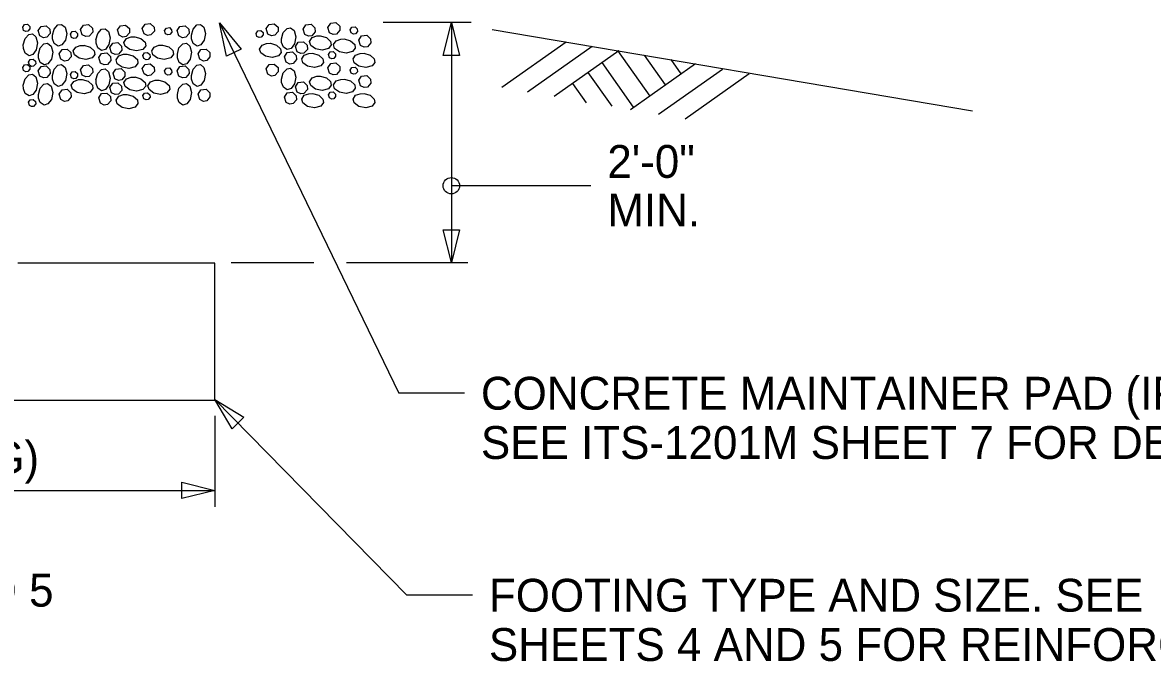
# Model space of a CAD drawing. Extents: x 3829340 to 3831660, y 499389 to 501171.
# Drawn here: x 3829574 to 3829677.1, y 499641 to 499699.3 of the extents above; entities that cross this region are included whole.
import ezdxf

# ---------------------------------------------------------------- set-up
doc = ezdxf.new("R2010")
doc.units = 0
for name, color, linetype in [('Barrier', 7, 'Continuous'), ('DIM TXT', 7, 'Continuous'), ('foundation', 7, 'Continuous'), ('grade', 7, 'Continuous')]:
    doc.layers.add(name, color=color, linetype=linetype)

msp = doc.modelspace()

# ---------------------------------------------------------------- linework, layer by layer
at = {"layer": 'Barrier'}
for points in [[(3829574.07, 499698.59), (3829573.98, 499698.89), (3829574.14, 499699.12), (3829574.42, 499699.15), (3829574.63, 499698.96), (3829574.64, 499698.73), (3829574.45, 499698.52), (3829574.27, 499698.5), (3829574.07, 499698.59)], [(3829575.55, 499698.09), (3829575.39, 499698.57), (3829575.66, 499698.96), (3829576.12, 499699.02), (3829576.47, 499698.69), (3829576.49, 499698.32), (3829576.18, 499697.97), (3829575.88, 499697.92), (3829575.55, 499698.09)], [(3829576.7, 499698.14), (3829576.86, 499698.71), (3829577.2, 499699.09), (3829577.53, 499699.14), (3829577.85, 499698.89), (3829578, 499698.31), (3829577.88, 499697.69), (3829577.57, 499697.26), (3829577.22, 499697.15), (3829576.86, 499697.39), (3829576.71, 499697.81), (3829576.7, 499698.17)], [(3829578.43, 499697.95), (3829578.34, 499698.24), (3829578.5, 499698.48), (3829578.78, 499698.51), (3829578.99, 499698.32), (3829579, 499698.09), (3829578.82, 499697.88), (3829578.64, 499697.85), (3829578.43, 499697.95)], [(3829579.42, 499698.18), (3829579.27, 499698.67), (3829579.53, 499699.06), (3829580, 499699.12), (3829580.35, 499698.79), (3829580.37, 499698.42), (3829580.06, 499698.07), (3829579.76, 499698.02), (3829579.42, 499698.18)], [(3829580.67, 499697.74), (3829580.83, 499698.31), (3829581.17, 499698.69), (3829581.5, 499698.74), (3829581.83, 499698.49), (3829581.98, 499697.91), (3829581.86, 499697.3), (3829581.54, 499696.86), (3829581.19, 499696.76), (3829580.84, 499696.99), (3829580.68, 499697.41), (3829580.68, 499697.77)], [(3829582.8, 499698.14), (3829582.64, 499698.63), (3829582.9, 499699.02), (3829583.37, 499699.08), (3829583.72, 499698.75), (3829583.74, 499698.38), (3829583.43, 499698.03), (3829583.13, 499697.98), (3829582.8, 499698.14)], [(3829585.06, 499698.29), (3829584.9, 499698.77), (3829585.17, 499699.17), (3829585.63, 499699.22), (3829585.98, 499698.9), (3829586, 499698.52), (3829585.69, 499698.17), (3829585.39, 499698.12), (3829585.06, 499698.29)], [(3829587.03, 499698.28), (3829586.94, 499698.57), (3829587.1, 499698.8), (3829587.38, 499698.84), (3829587.58, 499698.64), (3829587.6, 499698.42), (3829587.41, 499698.21), (3829587.23, 499698.18), (3829587.03, 499698.28)], [(3829588.23, 499698.09), (3829588.07, 499698.57), (3829588.33, 499698.96), (3829588.8, 499699.02), (3829589.15, 499698.69), (3829589.17, 499698.32), (3829588.86, 499697.97), (3829588.56, 499697.92), (3829588.23, 499698.09)], [(3829589.38, 499698.14), (3829589.54, 499698.71), (3829589.88, 499699.09), (3829590.21, 499699.14), (3829590.53, 499698.89), (3829590.68, 499698.31), (3829590.56, 499697.69), (3829590.25, 499697.26), (3829589.9, 499697.15), (3829589.54, 499697.39), (3829589.39, 499697.81), (3829589.38, 499698.17)], [(3829595.37, 499698.03), (3829595.28, 499698.32), (3829595.44, 499698.56), (3829595.72, 499698.59), (3829595.93, 499698.39), (3829595.94, 499698.17), (3829595.76, 499697.96), (3829595.58, 499697.93), (3829595.37, 499698.03)], [(3829596.36, 499698.26), (3829596.21, 499698.75), (3829596.47, 499699.14), (3829596.94, 499699.2), (3829597.29, 499698.87), (3829597.31, 499698.49), (3829597, 499698.14), (3829596.7, 499698.1), (3829596.36, 499698.26)], [(3829597.61, 499697.82), (3829597.77, 499698.39), (3829598.11, 499698.77), (3829598.44, 499698.82), (3829598.77, 499698.57), (3829598.92, 499697.99), (3829598.8, 499697.37), (3829598.48, 499696.94), (3829598.13, 499696.83), (3829597.78, 499697.07), (3829597.62, 499697.49), (3829597.62, 499697.85)], [(3829599.74, 499698.22), (3829599.58, 499698.71), (3829599.84, 499699.1), (3829600.31, 499699.16), (3829600.66, 499698.83), (3829600.68, 499698.46), (3829600.37, 499698.1), (3829600.07, 499698.06), (3829599.74, 499698.22)], [(3829602, 499698.36), (3829601.84, 499698.85), (3829602.11, 499699.24), (3829602.57, 499699.3), (3829602.92, 499698.97), (3829602.94, 499698.6), (3829602.63, 499698.25), (3829602.33, 499698.2), (3829602, 499698.36)], [(3829603.97, 499698.36), (3829603.88, 499698.65), (3829604.03, 499698.88), (3829604.32, 499698.92), (3829604.52, 499698.72), (3829604.54, 499698.5), (3829604.35, 499698.29), (3829604.17, 499698.26), (3829603.97, 499698.36)], [(3829574.04, 499697.27), (3829574.2, 499697.84), (3829574.54, 499698.21), (3829574.87, 499698.27), (3829575.19, 499698.01), (3829575.34, 499697.44), (3829575.22, 499696.82), (3829574.91, 499696.39), (3829574.56, 499696.28), (3829574.2, 499696.52), (3829574.05, 499696.94), (3829574.04, 499697.29)], [(3829582.09, 499696.55), (3829581.93, 499697.04), (3829582.2, 499697.43), (3829582.67, 499697.49), (3829583.01, 499697.16), (3829583.03, 499696.79), (3829582.72, 499696.43), (3829582.42, 499696.39), (3829582.09, 499696.55)], [(3829584.21, 499698.01), (3829584.78, 499697.85), (3829585.15, 499697.51), (3829585.21, 499697.18), (3829584.95, 499696.86), (3829584.38, 499696.71), (3829583.76, 499696.83), (3829583.33, 499697.14), (3829583.22, 499697.49), (3829583.46, 499697.85), (3829583.88, 499698), (3829584.24, 499698.01)], [(3829599.03, 499696.63), (3829598.87, 499697.12), (3829599.14, 499697.51), (3829599.61, 499697.56), (3829599.95, 499697.24), (3829599.97, 499696.86), (3829599.66, 499696.51), (3829599.36, 499696.47), (3829599.03, 499696.63)], [(3829601.15, 499698.09), (3829601.72, 499697.93), (3829602.09, 499697.59), (3829602.15, 499697.26), (3829601.89, 499696.94), (3829601.32, 499696.79), (3829600.7, 499696.91), (3829600.27, 499697.22), (3829600.16, 499697.57), (3829600.4, 499697.93), (3829600.82, 499698.08), (3829601.18, 499698.09)], [(3829603.34, 499697.81), (3829603.91, 499697.65), (3829604.29, 499697.31), (3829604.34, 499696.98), (3829604.09, 499696.66), (3829603.51, 499696.5), (3829602.89, 499696.62), (3829602.46, 499696.94), (3829602.35, 499697.29), (3829602.59, 499697.64), (3829603.01, 499697.8), (3829603.37, 499697.81)], [(3829604.81, 499697.21), (3829604.66, 499697.7), (3829604.92, 499698.09), (3829605.39, 499698.15), (3829605.74, 499697.82), (3829605.75, 499697.44), (3829605.45, 499697.09), (3829605.14, 499697.05), (3829604.81, 499697.21)], [(3829575.42, 499696.42), (3829575.58, 499696.99), (3829575.92, 499697.36), (3829576.25, 499697.42), (3829576.57, 499697.16), (3829576.72, 499696.59), (3829576.6, 499695.97), (3829576.29, 499695.54), (3829575.94, 499695.43), (3829575.58, 499695.67), (3829575.43, 499696.09), (3829575.42, 499696.44)], [(3829577.47, 499695.95), (3829577.31, 499696.44), (3829577.58, 499696.83), (3829578.04, 499696.88), (3829578.39, 499696.56), (3829578.41, 499696.18), (3829578.1, 499695.83), (3829577.8, 499695.79), (3829577.47, 499695.95)], [(3829579.57, 499697.23), (3829580.14, 499697.06), (3829580.52, 499696.73), (3829580.58, 499696.4), (3829580.32, 499696.08), (3829579.75, 499695.93), (3829579.13, 499696.04), (3829578.7, 499696.36), (3829578.59, 499696.71), (3829578.82, 499697.06), (3829579.24, 499697.22), (3829579.6, 499697.22)], [(3829581.09, 499695.61), (3829580.93, 499696.1), (3829581.19, 499696.49), (3829581.66, 499696.54), (3829582.01, 499696.22), (3829582.03, 499695.84), (3829581.72, 499695.49), (3829581.42, 499695.45), (3829581.09, 499695.61)], [(3829585.05, 499696.01), (3829584.95, 499696.3), (3829585.11, 499696.54), (3829585.39, 499696.57), (3829585.6, 499696.38), (3829585.61, 499696.15), (3829585.43, 499695.94), (3829585.25, 499695.91), (3829585.05, 499696.01)], [(3829586.74, 499697.24), (3829587.31, 499697.08), (3829587.69, 499696.74), (3829587.74, 499696.41), (3829587.49, 499696.08), (3829586.91, 499695.93), (3829586.3, 499696.05), (3829585.86, 499696.37), (3829585.76, 499696.72), (3829585.99, 499697.07), (3829586.41, 499697.23), (3829586.77, 499697.24)], [(3829588.1, 499696.42), (3829588.25, 499696.99), (3829588.6, 499697.36), (3829588.92, 499697.42), (3829589.24, 499697.16), (3829589.4, 499696.59), (3829589.28, 499695.97), (3829588.96, 499695.54), (3829588.61, 499695.43), (3829588.26, 499695.67), (3829588.11, 499696.09), (3829588.1, 499696.44)], [(3829590.15, 499695.95), (3829589.99, 499696.44), (3829590.25, 499696.83), (3829590.72, 499696.88), (3829591.07, 499696.56), (3829591.08, 499696.18), (3829590.78, 499695.83), (3829590.48, 499695.79), (3829590.15, 499695.95)], [(3829596.59, 499697.41), (3829597.15, 499697.25), (3829597.53, 499696.91), (3829597.59, 499696.58), (3829597.33, 499696.26), (3829596.76, 499696.11), (3829596.14, 499696.23), (3829595.71, 499696.54), (3829595.6, 499696.89), (3829595.83, 499697.25), (3829596.25, 499697.4), (3829596.61, 499697.41)], [(3829598.03, 499695.69), (3829597.87, 499696.18), (3829598.13, 499696.57), (3829598.6, 499696.62), (3829598.95, 499696.3), (3829598.97, 499695.92), (3829598.66, 499695.57), (3829598.36, 499695.52), (3829598.03, 499695.69)], [(3829600.44, 499696.5), (3829601.01, 499696.34), (3829601.39, 499696), (3829601.44, 499695.67), (3829601.19, 499695.35), (3829600.61, 499695.2), (3829599.99, 499695.32), (3829599.56, 499695.63), (3829599.46, 499695.98), (3829599.69, 499696.33), (3829600.11, 499696.49), (3829600.47, 499696.5)], [(3829601.99, 499696.09), (3829601.89, 499696.38), (3829602.05, 499696.62), (3829602.33, 499696.65), (3829602.54, 499696.45), (3829602.55, 499696.23), (3829602.37, 499696.02), (3829602.19, 499695.99), (3829601.99, 499696.09)], [(3829605.13, 499696.5), (3829605.7, 499696.34), (3829606.07, 499696), (3829606.13, 499695.67), (3829605.87, 499695.35), (3829605.3, 499695.2), (3829604.68, 499695.32), (3829604.25, 499695.63), (3829604.14, 499695.98), (3829604.37, 499696.33), (3829604.79, 499696.49), (3829605.15, 499696.5)], [(3829574.07, 499694.92), (3829573.98, 499695.21), (3829574.14, 499695.45), (3829574.42, 499695.48), (3829574.63, 499695.28), (3829574.64, 499695.06), (3829574.45, 499694.85), (3829574.27, 499694.82), (3829574.07, 499694.92)], [(3829574.6, 499695.4), (3829574.51, 499695.69), (3829574.67, 499695.93), (3829574.95, 499695.96), (3829575.16, 499695.77), (3829575.17, 499695.54), (3829574.98, 499695.33), (3829574.8, 499695.3), (3829574.6, 499695.4)], [(3829576.7, 499694.47), (3829576.86, 499695.04), (3829577.2, 499695.41), (3829577.53, 499695.47), (3829577.85, 499695.21), (3829578, 499694.64), (3829577.88, 499694.02), (3829577.57, 499693.59), (3829577.22, 499693.48), (3829576.86, 499693.72), (3829576.71, 499694.14), (3829576.7, 499694.49)], [(3829579.42, 499694.51), (3829579.27, 499695), (3829579.53, 499695.39), (3829580, 499695.44), (3829580.35, 499695.12), (3829580.37, 499694.74), (3829580.06, 499694.39), (3829579.76, 499694.35), (3829579.42, 499694.51)], [(3829583.5, 499696.42), (3829584.07, 499696.26), (3829584.45, 499695.92), (3829584.5, 499695.59), (3829584.25, 499695.27), (3829583.67, 499695.12), (3829583.05, 499695.24), (3829582.62, 499695.55), (3829582.52, 499695.9), (3829582.75, 499696.26), (3829583.17, 499696.41), (3829583.53, 499696.42)], [(3829585.06, 499694.61), (3829584.9, 499695.1), (3829585.17, 499695.49), (3829585.63, 499695.55), (3829585.98, 499695.22), (3829586, 499694.84), (3829585.69, 499694.49), (3829585.39, 499694.45), (3829585.06, 499694.61)], [(3829589.38, 499694.47), (3829589.54, 499695.04), (3829589.88, 499695.41), (3829590.21, 499695.47), (3829590.53, 499695.21), (3829590.68, 499694.64), (3829590.56, 499694.02), (3829590.25, 499693.59), (3829589.9, 499693.48), (3829589.54, 499693.72), (3829589.39, 499694.14), (3829589.38, 499694.49)], [(3829596.36, 499694.59), (3829596.21, 499695.08), (3829596.47, 499695.47), (3829596.94, 499695.52), (3829597.29, 499695.2), (3829597.31, 499694.82), (3829597, 499694.47), (3829596.7, 499694.42), (3829596.36, 499694.59)], [(3829602, 499694.69), (3829601.84, 499695.18), (3829602.11, 499695.57), (3829602.57, 499695.62), (3829602.92, 499695.3), (3829602.94, 499694.92), (3829602.63, 499694.57), (3829602.33, 499694.53), (3829602, 499694.69)], [(3829574.04, 499693.59), (3829574.2, 499694.16), (3829574.54, 499694.54), (3829574.87, 499694.59), (3829575.19, 499694.34), (3829575.34, 499693.76), (3829575.22, 499693.14), (3829574.91, 499692.72), (3829574.56, 499692.61), (3829574.2, 499692.84), (3829574.05, 499693.26), (3829574.04, 499693.62)], [(3829575.55, 499694.41), (3829575.39, 499694.9), (3829575.66, 499695.29), (3829576.12, 499695.34), (3829576.47, 499695.02), (3829576.49, 499694.64), (3829576.18, 499694.29), (3829575.88, 499694.25), (3829575.55, 499694.41)], [(3829578.43, 499694.27), (3829578.34, 499694.57), (3829578.5, 499694.8), (3829578.78, 499694.84), (3829578.99, 499694.64), (3829579, 499694.42), (3829578.82, 499694.2), (3829578.64, 499694.18), (3829578.43, 499694.27)], [(3829580.67, 499694.07), (3829580.83, 499694.64), (3829581.17, 499695.02), (3829581.5, 499695.07), (3829581.83, 499694.81), (3829581.98, 499694.24), (3829581.86, 499693.62), (3829581.54, 499693.19), (3829581.19, 499693.08), (3829580.84, 499693.31), (3829580.68, 499693.74), (3829580.68, 499694.09)], [(3829582.38, 499694.18), (3829582.23, 499694.67), (3829582.49, 499695.06), (3829582.96, 499695.12), (3829583.31, 499694.79), (3829583.32, 499694.42), (3829583.02, 499694.06), (3829582.72, 499694.02), (3829582.38, 499694.18)], [(3829587.03, 499694.61), (3829586.94, 499694.89), (3829587.1, 499695.13), (3829587.38, 499695.16), (3829587.58, 499694.97), (3829587.6, 499694.74), (3829587.41, 499694.53), (3829587.23, 499694.5), (3829587.03, 499694.61)], [(3829588.23, 499694.41), (3829588.07, 499694.9), (3829588.33, 499695.29), (3829588.8, 499695.34), (3829589.15, 499695.02), (3829589.17, 499694.64), (3829588.86, 499694.29), (3829588.56, 499694.25), (3829588.23, 499694.41)], [(3829597.61, 499694.15), (3829597.77, 499694.72), (3829598.11, 499695.09), (3829598.44, 499695.15), (3829598.77, 499694.89), (3829598.92, 499694.32), (3829598.8, 499693.7), (3829598.48, 499693.27), (3829598.13, 499693.16), (3829597.78, 499693.39), (3829597.62, 499693.82), (3829597.62, 499694.17)], [(3829601.15, 499694.42), (3829601.72, 499694.26), (3829602.09, 499693.91), (3829602.15, 499693.59), (3829601.89, 499693.26), (3829601.32, 499693.11), (3829600.7, 499693.23), (3829600.27, 499693.55), (3829600.16, 499693.9), (3829600.4, 499694.25), (3829600.82, 499694.4), (3829601.18, 499694.41)], [(3829603.97, 499694.68), (3829603.88, 499694.97), (3829604.03, 499695.21), (3829604.32, 499695.24), (3829604.52, 499695.05), (3829604.54, 499694.82), (3829604.35, 499694.61), (3829604.17, 499694.58), (3829603.97, 499694.68)], [(3829604.81, 499693.54), (3829604.66, 499694.03), (3829604.92, 499694.42), (3829605.39, 499694.47), (3829605.74, 499694.15), (3829605.75, 499693.77), (3829605.45, 499693.42), (3829605.14, 499693.38), (3829604.81, 499693.54)], [(3829575.42, 499692.74), (3829575.58, 499693.31), (3829575.92, 499693.69), (3829576.25, 499693.74), (3829576.57, 499693.49), (3829576.72, 499692.91), (3829576.6, 499692.29), (3829576.29, 499691.87), (3829575.94, 499691.76), (3829575.58, 499691.99), (3829575.43, 499692.41), (3829575.42, 499692.77)], [(3829579.4, 499694.1), (3829579.97, 499693.94), (3829580.35, 499693.6), (3829580.4, 499693.27), (3829580.15, 499692.95), (3829579.58, 499692.8), (3829578.95, 499692.92), (3829578.53, 499693.23), (3829578.42, 499693.58), (3829578.65, 499693.93), (3829579.07, 499694.09), (3829579.43, 499694.09)], [(3829582.09, 499692.88), (3829581.93, 499693.37), (3829582.2, 499693.76), (3829582.67, 499693.81), (3829583.01, 499693.49), (3829583.03, 499693.11), (3829582.72, 499692.76), (3829582.42, 499692.72), (3829582.09, 499692.88)], [(3829584.21, 499694.34), (3829584.78, 499694.18), (3829585.15, 499693.84), (3829585.21, 499693.51), (3829584.95, 499693.19), (3829584.38, 499693.04), (3829583.76, 499693.15), (3829583.33, 499693.47), (3829583.22, 499693.82), (3829583.46, 499694.17), (3829583.88, 499694.33), (3829584.24, 499694.33)], [(3829586.4, 499694.05), (3829586.97, 499693.9), (3829587.35, 499693.55), (3829587.4, 499693.23), (3829587.15, 499692.9), (3829586.57, 499692.75), (3829585.95, 499692.87), (3829585.52, 499693.19), (3829585.41, 499693.54), (3829585.65, 499693.89), (3829586.07, 499694.05), (3829586.43, 499694.05)], [(3829588.1, 499692.74), (3829588.25, 499693.31), (3829588.6, 499693.69), (3829588.92, 499693.74), (3829589.24, 499693.49), (3829589.4, 499692.91), (3829589.28, 499692.29), (3829588.96, 499691.87), (3829588.61, 499691.76), (3829588.26, 499691.99), (3829588.11, 499692.41), (3829588.1, 499692.77)], [(3829599.03, 499692.96), (3829598.87, 499693.44), (3829599.14, 499693.84), (3829599.61, 499693.89), (3829599.95, 499693.57), (3829599.97, 499693.19), (3829599.66, 499692.84), (3829599.36, 499692.79), (3829599.03, 499692.96)], [(3829603.34, 499694.13), (3829603.91, 499693.98), (3829604.29, 499693.63), (3829604.34, 499693.31), (3829604.09, 499692.98), (3829603.51, 499692.83), (3829602.89, 499692.95), (3829602.46, 499693.26), (3829602.35, 499693.61), (3829602.59, 499693.97), (3829603.01, 499694.12), (3829603.37, 499694.13)], [(3829577.47, 499692.27), (3829577.31, 499692.76), (3829577.58, 499693.15), (3829578.04, 499693.21), (3829578.39, 499692.88), (3829578.41, 499692.51), (3829578.1, 499692.16), (3829577.8, 499692.11), (3829577.47, 499692.27)], [(3829581.09, 499691.94), (3829580.93, 499692.43), (3829581.19, 499692.82), (3829581.66, 499692.87), (3829582.01, 499692.55), (3829582.03, 499692.17), (3829581.72, 499691.82), (3829581.42, 499691.77), (3829581.09, 499691.94)], [(3829583.5, 499692.75), (3829584.07, 499692.59), (3829584.45, 499692.24), (3829584.5, 499691.92), (3829584.25, 499691.59), (3829583.67, 499691.44), (3829583.05, 499691.56), (3829582.62, 499691.88), (3829582.52, 499692.23), (3829582.75, 499692.58), (3829583.17, 499692.73), (3829583.53, 499692.74)], [(3829585.05, 499692.34), (3829584.95, 499692.63), (3829585.11, 499692.86), (3829585.39, 499692.9), (3829585.6, 499692.7), (3829585.61, 499692.48), (3829585.43, 499692.27), (3829585.25, 499692.24), (3829585.05, 499692.34)], [(3829590.15, 499692.27), (3829589.99, 499692.76), (3829590.25, 499693.15), (3829590.72, 499693.21), (3829591.07, 499692.88), (3829591.08, 499692.51), (3829590.78, 499692.16), (3829590.48, 499692.11), (3829590.15, 499692.27)], [(3829598.03, 499692.01), (3829597.87, 499692.5), (3829598.13, 499692.89), (3829598.6, 499692.95), (3829598.95, 499692.62), (3829598.97, 499692.25), (3829598.66, 499691.9), (3829598.36, 499691.85), (3829598.03, 499692.01)], [(3829600.44, 499692.82), (3829601.01, 499692.66), (3829601.39, 499692.32), (3829601.44, 499692), (3829601.19, 499691.67), (3829600.61, 499691.52), (3829599.99, 499691.64), (3829599.56, 499691.96), (3829599.46, 499692.3), (3829599.69, 499692.66), (3829600.11, 499692.81), (3829600.47, 499692.82)], [(3829601.99, 499692.42), (3829601.89, 499692.71), (3829602.05, 499692.94), (3829602.33, 499692.97), (3829602.54, 499692.78), (3829602.55, 499692.56), (3829602.37, 499692.34), (3829602.19, 499692.32), (3829601.99, 499692.42)], [(3829605.13, 499692.82), (3829605.7, 499692.66), (3829606.07, 499692.32), (3829606.13, 499692), (3829605.87, 499691.67), (3829605.3, 499691.52), (3829604.68, 499691.64), (3829604.25, 499691.96), (3829604.14, 499692.3), (3829604.37, 499692.66), (3829604.79, 499692.81), (3829605.15, 499692.82)], [(3829574.6, 499691.72), (3829574.51, 499692.02), (3829574.67, 499692.25), (3829574.95, 499692.29), (3829575.16, 499692.09), (3829575.17, 499691.87), (3829574.98, 499691.65), (3829574.8, 499691.63), (3829574.6, 499691.72)]]:
    msp.add_lwpolyline(points, dxfattribs=at)
at = {"layer": 'DIM TXT'}
for p, q in [((3829591.95, 499699.27), (3829608.31, 499665.45)), ((3829614.91, 499699.3), (3829606.88, 499699.3)), ((3829613.11, 499699.3), (3829613.11, 499677.38)), ((3829625.85, 499684.4), (3829613.11, 499684.4)), ((3829593.02, 499677.38), (3829600.55, 499677.38)), ((3829593.02, 499677.38), (3829600.55, 499677.38)), ((3829603.55, 499677.38), (3829614.61, 499677.38)), ((3829603.55, 499677.38), (3829614.61, 499677.38)), ((3829591.52, 499664.88), (3829609.04, 499647)), ((3829614.31, 499665.45), (3829608.31, 499665.45)), ((3829591.52, 499663.38), (3829591.52, 499655.08)), ((3829529.02, 499656.58), (3829591.52, 499656.58)), ((3829615.04, 499647), (3829609.04, 499647))]:
    msp.add_line(p, q, dxfattribs=at)
for points in [[(3829592.58, 499696.24), (3829591.95, 499699.27), (3829593.93, 499696.89)], [(3829612.36, 499696.3), (3829613.11, 499699.3), (3829613.86, 499696.3)], [(3829613.86, 499680.38), (3829613.11, 499677.38), (3829612.36, 499680.38)], [(3829593.09, 499662.21), (3829591.52, 499664.88), (3829594.16, 499663.26)], [(3829588.52, 499657.33), (3829591.52, 499656.58), (3829588.52, 499655.83)]]:
    msp.add_lwpolyline(points, close=True, dxfattribs=at)
msp.add_circle((3829613.11, 499684.4), 0.75, dxfattribs=at)
at = {"layer": 'foundation'}
msp.add_lwpolyline([(3829546.99, 499677.33), (3829529.02, 499677.33), (3829529.02, 499664.83), (3829591.52, 499664.83), (3829591.52, 499677.33), (3829573.55, 499677.33)], dxfattribs=at)
at = {"layer": 'grade'}
for p, q in [((3829616.85, 499698.68), (3829660.69, 499691.23)), ((3829617.72, 499693.39), (3829623.59, 499697.54)), ((3829620.06, 499692.98), (3829625.97, 499697.16)), ((3829622.49, 499692.57), (3829628.39, 499696.74)), ((3829628.28, 499696.76), (3829631.23, 499692.59)), ((3829626.84, 499695.65), (3829629.72, 499691.57)), ((3829629.46, 499691.37), (3829635.4, 499695.56)), ((3829630.71, 499696.34), (3829632.63, 499693.63)), ((3829633.16, 499695.92), (3829634.07, 499694.63)), ((3829625.58, 499694.75), (3829627.77, 499691.66)), ((3829632.02, 499690.93), (3829637.86, 499695.06)), ((3829634.45, 499690.51), (3829640.29, 499694.64)), ((3829624.16, 499693.75), (3829625.41, 499691.98))]:
    msp.add_line(p, q, dxfattribs=at)

# ---------------------------------------------------------------- texts
at = {"layer": 'DIM TXT'}
for s, height, p in [('2\'-0"', 3, (3829627.35, 499685.12)), ('MIN.', 3, (3829627.35, 499680.68)), ('CONCRETE MAINTAINER PAD (IF REQUIRED). ', 2.9999, (3829615.81, 499663.95)), ('SEE ITS-1201M SHEET 7 FOR DETAILS.', 2.9999, (3829615.81, 499659.45)), ('FOOTING WIDTH (G)', 2.9999, (3829536.04, 499658.08)), ('SEE SHEETS 4 AND 5', 2.9999, (3829535.33, 499645.96)), ('FOOTING TYPE AND SIZE. SEE', 2.9999, (3829616.54, 499645.5)), ('SHEETS 4 AND 5 FOR REINFORCEMENT', 2.9999, (3829616.54, 499641))]:
    msp.add_text(s, height=height, dxfattribs=at).set_placement(p)

doc.saveas('drawing.dxf')
